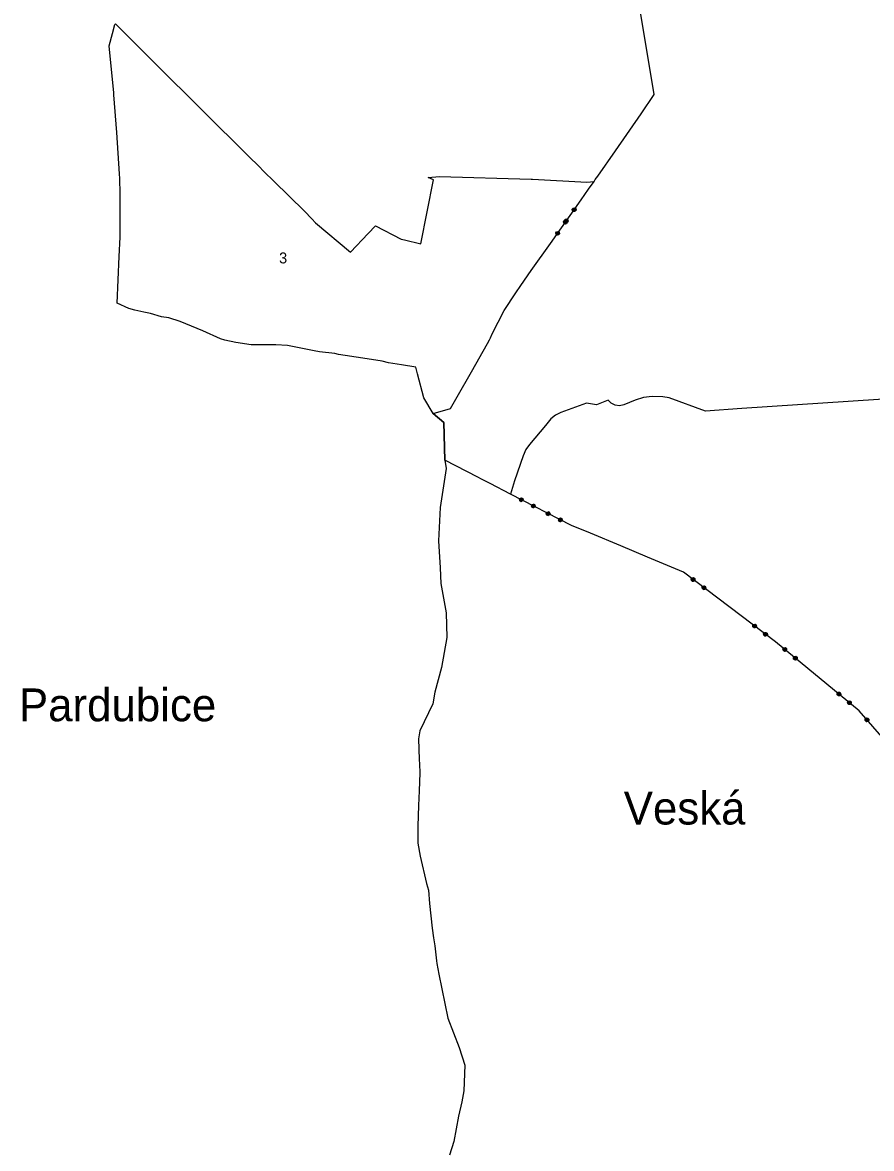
# Model space of a CAD drawing. Extents: x -643242 to -638517, y -1061413 to -1055378.
# Drawn here: x -643018 to -642086, y -1060771 to -1059534 of the extents above; entities that cross this region are included whole.
import ezdxf

# ---------------------------------------------------------------- set-up
doc = ezdxf.new("R2010")
doc.units = 0
for name, color, linetype in [('HRA_KU', 7, 'Continuous'), ('HRA_OB', 7, 'Continuous'), ('KU_OST', 7, 'Continuous'), ('LES_ZV', 7, 'Continuous'), ('OVNE_SET', 7, 'Continuous'), ('OVNI_SET', 7, 'Continuous'), ('POZN', 7, 'Continuous')]:
    doc.layers.add(name, color=color, linetype=linetype)

msp = doc.modelspace()

# ---------------------------------------------------------------- linework, layer by layer
at = {"layer": 'HRA_KU'}
for points in [[(-642525.1, -1059917.5), (-642507.5, -1059886.4), (-642505.3, -1059882.6), (-642504.2, -1059880.2), (-642502.2, -1059875.8), (-642489, -1059850.2), (-642476.2, -1059830.9), (-642470.7, -1059822.9), (-642459.4, -1059806.4), (-642438.4, -1059776.8), (-642404.7, -1059728.7), (-642396.6, -1059717), (-642390.4, -1059708.5)], [(-642413.4, -1059737.8), (-642411.8, -1059737.5), (-642410.5, -1059738.4), (-642410.2, -1059740), (-642411.2, -1059741.3), (-642412.7, -1059741.6), (-642414.1, -1059740.7), (-642414.3, -1059739.1), (-642413.4, -1059737.8), (-642413.3, -1059738.1), (-642414.2, -1059739.2), (-642414, -1059739.9), (-642412.7, -1059737.9), (-642412, -1059737.8), (-642413.9, -1059740.6), (-642413.5, -1059740.8), (-642411.6, -1059738.1), (-642411.2, -1059738.4), (-642413.1, -1059741.1), (-642412.7, -1059741.4), (-642410.8, -1059738.6), (-642410.7, -1059739.3), (-642412.1, -1059741.3), (-642411.4, -1059741.2), (-642410.6, -1059740)], [(-642423, -1059751.5), (-642421.4, -1059751.2), (-642420.1, -1059752.1), (-642419.8, -1059753.7), (-642420.7, -1059755), (-642422.3, -1059755.3), (-642423.6, -1059754.4), (-642423.9, -1059752.8), (-642423, -1059751.5), (-642422.9, -1059751.7), (-642423.7, -1059752.9), (-642423.6, -1059753.6), (-642422.2, -1059751.6), (-642421.6, -1059751.5), (-642423.5, -1059754.3), (-642423.1, -1059754.5), (-642421.2, -1059751.8), (-642420.8, -1059752.1), (-642422.7, -1059754.8), (-642422.3, -1059755.1), (-642420.4, -1059752.3), (-642420.3, -1059753), (-642421.6, -1059755), (-642421, -1059754.8), (-642420.1, -1059753.7)], [(-642422, -1059750.1), (-642420.4, -1059749.8), (-642419.1, -1059750.7), (-642418.8, -1059752.3), (-642419.7, -1059753.6), (-642421.3, -1059753.9), (-642422.7, -1059753), (-642422.9, -1059751.4), (-642422, -1059750.1), (-642421.8, -1059750.3), (-642422.7, -1059751.4), (-642422.6, -1059752.1), (-642421.2, -1059750.1), (-642420.5, -1059750), (-642422.4, -1059752.8), (-642422, -1059753), (-642420.1, -1059750.3), (-642419.7, -1059750.6), (-642421.7, -1059753.3), (-642421.3, -1059753.6), (-642419.3, -1059750.8), (-642419.2, -1059751.5), (-642420.6, -1059753.5), (-642419.9, -1059753.4), (-642419.1, -1059752.2)], [(-642431.6, -1059763.8), (-642430, -1059763.5), (-642428.7, -1059764.4), (-642428.4, -1059766), (-642429.3, -1059767.3), (-642430.9, -1059767.6), (-642432.2, -1059766.7), (-642432.5, -1059765.1), (-642431.6, -1059763.8), (-642431.4, -1059763.9), (-642432.2, -1059765.1), (-642432.1, -1059765.8), (-642430.7, -1059763.8), (-642430.1, -1059763.7), (-642432, -1059766.5), (-642431.6, -1059766.7), (-642429.7, -1059764), (-642429.3, -1059764.3), (-642431.2, -1059767), (-642430.8, -1059767.3), (-642428.9, -1059764.5), (-642428.8, -1059765.2), (-642430.2, -1059767.2), (-642429.5, -1059767), (-642428.7, -1059765.9)], [(-641984.1, -1060421.7), (-642099.2, -1060289.8), (-642191.1, -1060214.1), (-642292.1, -1060137.8), (-642331.8, -1060121.1), (-642360.8, -1060108.9), (-642394.4, -1060094.7), (-642415.3, -1060086.6), (-642482.2, -1060052), (-642504.7, -1060040.4), (-642508.3, -1060038.5), (-642514.2, -1060035.4), (-642518.2, -1060033.4)], [(-642472, -1060059.4), (-642472.5, -1060057.9), (-642471.7, -1060056.4), (-642470.2, -1060056), (-642468.8, -1060056.7), (-642468.3, -1060058.2), (-642469, -1060059.7), (-642470.6, -1060060.2), (-642472, -1060059.4), (-642471.7, -1060059.3), (-642470.5, -1060060), (-642469.8, -1060059.8), (-642471.9, -1060058.6), (-642472.1, -1060058), (-642469.2, -1060059.5), (-642468.9, -1060059.1), (-642471.9, -1060057.6), (-642471.7, -1060057.1), (-642468.7, -1060058.7), (-642468.5, -1060058.3), (-642471.5, -1060056.7), (-642470.8, -1060056.5), (-642468.7, -1060057.6), (-642468.9, -1060057), (-642470.2, -1060056.3)], [(-642458.7, -1060066.3), (-642459.2, -1060064.8), (-642458.4, -1060063.3), (-642456.9, -1060062.9), (-642455.4, -1060063.6), (-642455, -1060065.1), (-642455.7, -1060066.6), (-642457.2, -1060067.1), (-642458.7, -1060066.3), (-642458.5, -1060066.1), (-642457.2, -1060066.8), (-642456.6, -1060066.6), (-642458.7, -1060065.5), (-642458.9, -1060064.8), (-642455.9, -1060066.4), (-642455.7, -1060066), (-642458.7, -1060064.4), (-642458.5, -1060064), (-642455.5, -1060065.5), (-642455.3, -1060065.1), (-642458.3, -1060063.6), (-642457.6, -1060063.4), (-642455.5, -1060064.5), (-642455.7, -1060063.8), (-642457, -1060063.1)], [(-642442.5, -1060074.7), (-642442.9, -1060073.2), (-642442.2, -1060071.7), (-642440.7, -1060071.3), (-642439.2, -1060072), (-642438.7, -1060073.5), (-642439.5, -1060075), (-642441, -1060075.5), (-642442.5, -1060074.7), (-642442.2, -1060074.6), (-642440.9, -1060075.3), (-642440.3, -1060075), (-642442.4, -1060073.9), (-642442.6, -1060073.3), (-642439.6, -1060074.8), (-642439.4, -1060074.4), (-642442.4, -1060072.9), (-642442.2, -1060072.4), (-642439.2, -1060074), (-642438.9, -1060073.6), (-642441.9, -1060072), (-642441.3, -1060071.8), (-642439.2, -1060072.9), (-642439.4, -1060072.3), (-642440.6, -1060071.6)], [(-642429.1, -1060081.6), (-642429.6, -1060080.1), (-642428.9, -1060078.6), (-642427.3, -1060078.1), (-642425.9, -1060078.9), (-642425.4, -1060080.4), (-642426.2, -1060081.9), (-642427.7, -1060082.4), (-642429.1, -1060081.6), (-642429, -1060081.4), (-642427.7, -1060082.1), (-642427, -1060081.9), (-642429.2, -1060080.8), (-642429.4, -1060080.1), (-642426.4, -1060081.7), (-642426.2, -1060081.3), (-642429.2, -1060079.7), (-642428.9, -1060079.3), (-642426, -1060080.8), (-642425.7, -1060080.4), (-642428.7, -1060078.9), (-642428.1, -1060078.6), (-642425.9, -1060079.8), (-642426.1, -1060079.1), (-642427.4, -1060078.4)], [(-642283.4, -1060146.8), (-642283.6, -1060145.2), (-642282.6, -1060144), (-642281, -1060143.7), (-642279.7, -1060144.7), (-642279.5, -1060146.3), (-642280.5, -1060147.6), (-642282.1, -1060147.8), (-642283.4, -1060146.8), (-642283.1, -1060146.8), (-642281.9, -1060147.6), (-642281.3, -1060147.5), (-642283.2, -1060146.1), (-642283.3, -1060145.4), (-642280.6, -1060147.4), (-642280.3, -1060147.1), (-642283, -1060145), (-642282.7, -1060144.7), (-642280, -1060146.7), (-642279.7, -1060146.3), (-642282.4, -1060144.3), (-642281.7, -1060144.2), (-642279.8, -1060145.6), (-642279.9, -1060144.9), (-642281.1, -1060144.1)], [(-642271.4, -1060155.9), (-642271.6, -1060154.3), (-642270.7, -1060153), (-642269.1, -1060152.8), (-642267.8, -1060153.7), (-642267.5, -1060155.3), (-642268.5, -1060156.6), (-642270.1, -1060156.9), (-642271.4, -1060155.9), (-642271.2, -1060155.7), (-642270.1, -1060156.6), (-642269.4, -1060156.5), (-642271.3, -1060155.1), (-642271.4, -1060154.4), (-642268.7, -1060156.4), (-642268.4, -1060156), (-642271.1, -1060154), (-642270.8, -1060153.6), (-642268.1, -1060155.6), (-642267.9, -1060155.3), (-642270.5, -1060153.2), (-642269.9, -1060153.1), (-642268, -1060154.6), (-642268, -1060153.9), (-642269.2, -1060153)], [(-642215.8, -1060197.9), (-642216, -1060196.3), (-642215.1, -1060195), (-642213.5, -1060194.7), (-642212.2, -1060195.7), (-642212, -1060197.3), (-642212.9, -1060198.6), (-642214.5, -1060198.8), (-642215.8, -1060197.9), (-642215.5, -1060197.8), (-642214.4, -1060198.6), (-642213.7, -1060198.5), (-642215.6, -1060197.1), (-642215.7, -1060196.4), (-642213, -1060198.4), (-642212.8, -1060198.1), (-642215.4, -1060196), (-642215.1, -1060195.7), (-642212.5, -1060197.7), (-642212.2, -1060197.3), (-642214.9, -1060195.3), (-642214.2, -1060195.2), (-642212.3, -1060196.6), (-642212.4, -1060196), (-642213.5, -1060195.1)], [(-642203.9, -1060206.9), (-642204.1, -1060205.3), (-642203.1, -1060204), (-642201.5, -1060203.8), (-642200.2, -1060204.8), (-642200, -1060206.3), (-642201, -1060207.6), (-642202.6, -1060207.9), (-642203.9, -1060206.9), (-642203.7, -1060206.7), (-642202.5, -1060207.6), (-642201.8, -1060207.5), (-642203.8, -1060206.1), (-642203.8, -1060205.4), (-642201.2, -1060207.4), (-642200.9, -1060207), (-642203.6, -1060205), (-642203.3, -1060204.6), (-642200.6, -1060206.6), (-642200.3, -1060206.3), (-642203, -1060204.2), (-642202.3, -1060204.1), (-642200.4, -1060205.6), (-642200.5, -1060204.9), (-642201.6, -1060204.1)], [(-642182.7, -1060223.5), (-642182.9, -1060221.9), (-642181.8, -1060220.7), (-642180.2, -1060220.5), (-642179, -1060221.5), (-642178.8, -1060223.1), (-642179.8, -1060224.4), (-642181.4, -1060224.5), (-642182.7, -1060223.5), (-642182.4, -1060223.4), (-642181.3, -1060224.4), (-642180.6, -1060224.3), (-642182.5, -1060222.8), (-642182.5, -1060222.1), (-642179.9, -1060224.2), (-642179.6, -1060223.9), (-642182.2, -1060221.7), (-642181.9, -1060221.4), (-642179.3, -1060223.5), (-642179, -1060223.1), (-642181.6, -1060221), (-642180.9, -1060220.9), (-642179.1, -1060222.4), (-642179.2, -1060221.8), (-642180.3, -1060220.9)], [(-642171.1, -1060233.1), (-642171.3, -1060231.5), (-642170.2, -1060230.2), (-642168.6, -1060230.1), (-642167.4, -1060231.1), (-642167.2, -1060232.7), (-642168.3, -1060233.9), (-642169.9, -1060234.1), (-642171.1, -1060233.1), (-642170.9, -1060232.9), (-642169.8, -1060233.8), (-642169.1, -1060233.8), (-642171, -1060232.2), (-642171.1, -1060231.6), (-642168.5, -1060233.7), (-642168.2, -1060233.3), (-642170.7, -1060231.2), (-642170.4, -1060230.8), (-642167.9, -1060233), (-642167.5, -1060232.6), (-642170.1, -1060230.5), (-642169.5, -1060230.4), (-642167.6, -1060231.9), (-642167.7, -1060231.2), (-642168.8, -1060230.3)], [(-642123.3, -1060272.5), (-642123.4, -1060270.9), (-642122.4, -1060269.6), (-642120.8, -1060269.5), (-642119.5, -1060270.5), (-642119.4, -1060272.1), (-642120.4, -1060273.4), (-642122, -1060273.5), (-642123.3, -1060272.5), (-642123, -1060272.4), (-642121.9, -1060273.3), (-642121.2, -1060273.3), (-642123, -1060271.7), (-642123.1, -1060271.1), (-642120.5, -1060273.2), (-642120.2, -1060272.8), (-642122.8, -1060270.7), (-642122.5, -1060270.3), (-642119.9, -1060272.5), (-642119.6, -1060272.1), (-642122.2, -1060270), (-642121.5, -1060269.9), (-642119.7, -1060271.4), (-642119.7, -1060270.7), (-642120.8, -1060269.8)], [(-642111.7, -1060282), (-642111.9, -1060280.4), (-642110.8, -1060279.2), (-642109.2, -1060279), (-642108, -1060280.1), (-642107.8, -1060281.7), (-642108.8, -1060282.9), (-642110.5, -1060283.1), (-642111.7, -1060282), (-642111.5, -1060281.9), (-642110.4, -1060282.8), (-642109.7, -1060282.7), (-642111.6, -1060281.2), (-642111.6, -1060280.5), (-642109, -1060282.7), (-642108.7, -1060282.3), (-642111.3, -1060280.2), (-642111, -1060279.8), (-642108.4, -1060281.9), (-642108.1, -1060281.6), (-642110.7, -1060279.4), (-642110, -1060279.4), (-642108.2, -1060280.9), (-642108.3, -1060280.2), (-642109.4, -1060279.3)], [(-642092.5, -1060300.4), (-642092.4, -1060298.8), (-642091.2, -1060297.8), (-642089.6, -1060297.9), (-642088.5, -1060299.1), (-642088.6, -1060300.7), (-642089.8, -1060301.8), (-642091.4, -1060301.7), (-642092.5, -1060300.4), (-642092.2, -1060300.4), (-642091.3, -1060301.5), (-642090.6, -1060301.6), (-642092.2, -1060299.7), (-642092.1, -1060299.1), (-642089.9, -1060301.6), (-642089.5, -1060301.3), (-642091.8, -1060298.8), (-642091.4, -1060298.4), (-642089.2, -1060301), (-642088.8, -1060300.7), (-642091, -1060298.1), (-642090.4, -1060298.2), (-642088.8, -1060300), (-642088.7, -1060299.3), (-642089.7, -1060298.2)]]:
    msp.add_lwpolyline(points, dxfattribs=at)
at = {"layer": 'HRA_OB'}
msp.add_lwpolyline([(-642567, -1059963.6), (-642555.6, -1059973.5), (-642554.3, -1060014.6), (-642552.9, -1060023.8), (-642559.5, -1060066.5), (-642561.3, -1060103.3), (-642559.5, -1060132.9), (-642558.8, -1060150), (-642552.8, -1060182.2), (-642552.2, -1060209.5), (-642557.9, -1060242.3), (-642565.5, -1060269.3), (-642567.5, -1060282.2), (-642581.8, -1060312), (-642583.4, -1060320.8), (-642582.5, -1060343.3), (-642582.3, -1060348.4), (-642581.8, -1060358), (-642582.4, -1060378), (-642583.2, -1060393.9), (-642584.2, -1060416.7), (-642584, -1060435.4), (-642581.4, -1060449.5), (-642574.6, -1060479.7), (-642572.4, -1060486.9), (-642571.1, -1060501.7), (-642568.1, -1060528.5), (-642566.7, -1060539.3), (-642565.5, -1060548.1), (-642563.4, -1060564.5), (-642563, -1060567.3), (-642561.1, -1060579), (-642551.1, -1060627.6), (-642538.7, -1060659.8), (-642532.5, -1060679.2), (-642533.4, -1060707.2), (-642535.5, -1060719.4), (-642539.3, -1060735.2), (-642544.6, -1060763.1), (-642549.1, -1060777.9)], dxfattribs=at)
at = {"layer": 'LES_ZV'}
msp.add_lwpolyline([(-642567, -1059963.6), (-642548, -1059957.9), (-642540.7, -1059945), (-642525.1, -1059917.5)], dxfattribs=at)
at = {"layer": 'OVNE_SET'}
for points in [[(-642390.4, -1059708.5), (-642389, -1059706.5), (-642386.4, -1059702.8), (-642367, -1059674.8), (-642338.8, -1059634.2), (-642324.3, -1059613.3), (-642326.6, -1059599.7), (-642371.6, -1059330.2)], [(-642567, -1059963.6), (-642577.3, -1059946.1), (-642584.4, -1059919.7), (-642586.3, -1059912.5), (-642602.1, -1059910), (-642616.4, -1059907.7), (-642623.1, -1059906), (-642644.5, -1059902.8), (-642671.1, -1059898.6), (-642675.3, -1059897.7), (-642692.1, -1059895.6), (-642697.9, -1059894.8), (-642727.1, -1059888.7), (-642740.1, -1059888), (-642767, -1059888), (-642784.1, -1059885.4), (-642796, -1059882.8), (-642801, -1059881.6), (-642820.4, -1059872.7), (-642845.1, -1059862.5), (-642857.6, -1059858.4), (-642865.8, -1059857.1), (-642877.7, -1059853.8), (-642884.9, -1059852.1), (-642895, -1059849.8), (-642901.7, -1059848.2), (-642914.3, -1059842.4), (-642912.1, -1059791.2), (-642911.2, -1059769.9), (-642911.2, -1059755), (-642911.2, -1059725.3), (-642911.2, -1059722.3), (-642911.6, -1059705.5), (-642911.7, -1059700.4), (-642914.9, -1059654.9), (-642918.1, -1059613.4), (-642918.2, -1059611.3), (-642923.1, -1059559.8), (-642919.6, -1059546.2), (-642917, -1059536.4)], [(-641928.4, -1059938.1), (-642078, -1059948.1), (-642228, -1059958.1), (-642267.9, -1059960.8), (-642307.7, -1059946.4), (-642314.9, -1059945.1), (-642326.5, -1059944.7), (-642336, -1059946), (-642345.2, -1059948.8), (-642357.5, -1059953.9), (-642362.3, -1059954.9), (-642367.1, -1059954.3), (-642371.5, -1059952.2), (-642374.9, -1059948.7), (-642387.8, -1059954.1), (-642398.7, -1059952.2), (-642426.8, -1059962.4), (-642432.8, -1059965.1), (-642437.9, -1059969.4), (-642443.9, -1059976.6), (-642461.5, -1059997.4), (-642465.2, -1060002.8), (-642468.2, -1060009.9), (-642477.7, -1060037.4)], [(-642554.3, -1060014.6), (-642555.6, -1059973.5), (-642567, -1059963.6)], [(-642477.7, -1060037.4), (-642482.2, -1060052), (-642504.7, -1060040.4), (-642508.3, -1060038.5), (-642514.2, -1060035.4), (-642518.2, -1060033.4), (-642554.3, -1060014.6)]]:
    msp.add_lwpolyline(points, dxfattribs=at)
at = {"layer": 'OVNI_SET'}
for points in [[(-642752.7, -1059697.9), (-642759.1, -1059691.5), (-642769.2, -1059681.5), (-642873, -1059578.7), (-642916.3, -1059535.4), (-642917, -1059536.4)], [(-642752.7, -1059697.9), (-642742.2, -1059708.2), (-642708.7, -1059741.3), (-642700.6, -1059749.8), (-642696.5, -1059754.1), (-642658, -1059786.2), (-642638.6, -1059765.9), (-642630.5, -1059757.4), (-642602.3, -1059771.9), (-642598.6, -1059772.8), (-642580.8, -1059777.1)], [(-642580.8, -1059777.1), (-642566.8, -1059706.9), (-642572.6, -1059704.1), (-642560.2, -1059703.2), (-642459.6, -1059706), (-642458, -1059706), (-642398.4, -1059709.4), (-642390.4, -1059708.5)]]:
    msp.add_lwpolyline(points, dxfattribs=at)

# ---------------------------------------------------------------- texts
at = {"layer": 'KU_OST'}
for s, p in [('Pardubice', (-643022.3, -1060301.4)), ('Veská', (-642357.8, -1060414.8))]:
    msp.add_text(s, height=36, dxfattribs=at).set_placement(p)
at = {"layer": 'POZN'}
msp.add_text('3', height=12, dxfattribs=at).set_placement((-642736.5, -1059798.6))

doc.saveas('drawing.dxf')
